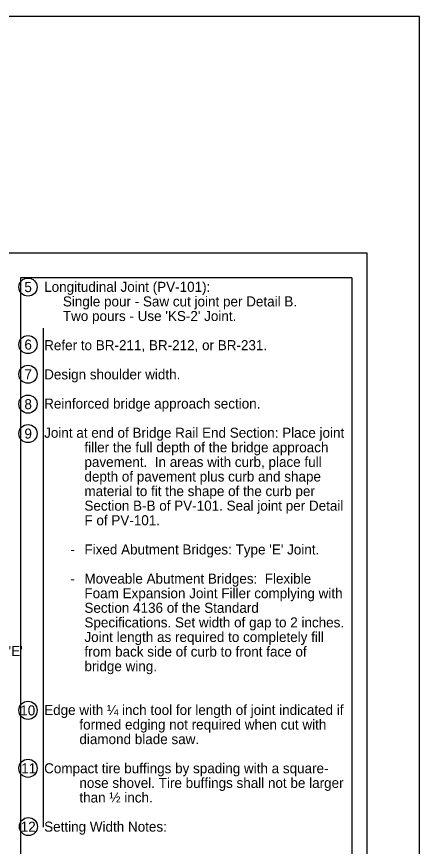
# Model space of a CAD drawing. Extents: x -2135039 to -2120895, y -2139150 to -2136566.
# Drawn here: x -2121695 to -2120895, y -2138216 to -2136566 of the extents above; entities that cross this region are included whole.
import ezdxf

# ---------------------------------------------------------------- set-up
doc = ezdxf.new("R2010")
doc.units = 0
for name, color, linetype in [('dsnDOTLogo', 7, 'Continuous'), ('dsnNonPlotable', 7, 'Continuous'), ('Level 1', 7, 'Continuous'), ('Level 2', 7, 'Continuous'), ('Level 3', 7, 'Continuous')]:
    doc.layers.add(name, color=color, linetype=linetype)

msp = doc.modelspace()

# ---------------------------------------------------------------- linework, layer by layer
at = {"layer": 'dsnDOTLogo'}
msp.add_lwpolyline([(-2124239, -2139150.4), (-2120895, -2139150.4), (-2120895, -2136566.4), (-2124239, -2136566.4)], close=True, dxfattribs=at)
at = {"layer": 'dsnNonPlotable'}
for p, q in [((-2121687.5, -2137085.9), (-2121687.5, -2138555.9)), ((-2121029.5, -2137085.9), (-2121687.5, -2137085.9)), ((-2121029.5, -2137085.9), (-2121029.5, -2138555.9)), ((-2121642.5, -2137185.9), (-2121642.5, -2138177.5))]:
    msp.add_line(p, q, dxfattribs=at)
at = {"layer": 'Level 1'}
msp.add_lwpolyline([(-2124134.5, -2137035.9), (-2120999.5, -2137035.9), (-2120999.5, -2139045.9), (-2124134.5, -2139045.9)], close=True, dxfattribs=at)
at = {"layer": 'Level 2'}
for centre in [(-2121672.5, -2137104.1), (-2121672.5, -2137218.4), (-2121672.5, -2137277.4), (-2121672.5, -2137336.8), (-2121672.5, -2137395.3), (-2121672.5, -2137945.4), (-2121672.5, -2138060.6), (-2121671.7, -2138176.5)]:
    msp.add_circle(centre, 18, dxfattribs=at)

# ---------------------------------------------------------------- texts
at = {"layer": 'Level 1'}
for s, p in [('5', (-2121679.7, -2137114.1)), ('Longitudinal Joint (PV-101):', (-2121640.4, -2137113.6)), ('     Single pour - Saw cut joint per Detail B.', (-2121640.4, -2137142.6)), ("     Two pours - Use 'KS-2' Joint.", (-2121640.4, -2137171.6)), ('6', (-2121679.6, -2137228.4)), ('Refer to BR-211, BR-212, or BR-231.', (-2121640.4, -2137229.6)), ('7', (-2121679.6, -2137287.4)), ('Design shoulder width.', (-2121640.4, -2137287.6)), ('8', (-2121679.6, -2137346.8)), ('Reinforced bridge approach section.', (-2121640.4, -2137345.6)), ('9', (-2121679.6, -2137405.3)), ('Joint at end of Bridge Rail End Section: Place joint ', (-2121640.4, -2137403.6)), ('filler the full depth of the bridge approach ', (-2121560.4, -2137432.6)), ('pavement.  In areas with curb, place full ', (-2121560.4, -2137461.6)), ('depth of pavement plus curb and shape ', (-2121560.4, -2137490.6)), ('material to fit the shape of the curb per ', (-2121560.4, -2137519.6)), ('Section B-B of PV-101. Seal joint per Detail ', (-2121560.4, -2137548.6)), ('F of PV-101.', (-2121560.4, -2137577.6)), ('       -', (-2121640.4, -2137635.6)), ("Fixed Abutment Bridges: Type 'E' Joint.", (-2121560.4, -2137635.6)), ('Moveable Abutment Bridges:  Flexible ', (-2121560.4, -2137693.6)), ('       -', (-2121640.4, -2137693.6)), ('Foam Expansion Joint Filler complying with ', (-2121560.4, -2137722.6)), ('Section 4136 of the Standard ', (-2121560.4, -2137751.6)), ('Specifications. Set width of gap to 2 inches.  ', (-2121560.4, -2137780.6)), ('Joint length as required to completely fill ', (-2121560.4, -2137809.6)), ('from back side of curb to front face of ', (-2121560.4, -2137838.6)), ('bridge wing.', (-2121560.4, -2137867.6)), ('Edge with ¼ inch tool for length of joint indicated if ', (-2121640.4, -2137954.6)), ('formed edging not required when cut with ', (-2121570.4, -2137983.6)), ('diamond blade saw.', (-2121570.4, -2138012.6)), ('Compact tire buffings by spading with a square-', (-2121640.4, -2138070.6)), ('nose shovel. Tire buffings shall not be larger ', (-2121570.4, -2138099.6)), ('than ½ inch.', (-2121570.4, -2138128.6)), ('Setting Width Notes:', (-2121640.4, -2138186.6))]:
    msp.add_text(s, height=20, dxfattribs=at).set_placement(p)
at = {"layer": 'Level 2'}
msp.add_text("See Detail 'E'", height=20, dxfattribs=at).set_placement((-2121841.9, -2137837.6))
at = {"layer": 'Level 3'}
for s, p in [('10', (-2121687.9, -2137955.5)), ('11', (-2121686, -2138070.7)), ('12', (-2121687, -2138186.7))]:
    msp.add_text(s, height=20, dxfattribs=at).set_placement(p)

doc.saveas('drawing.dxf')
